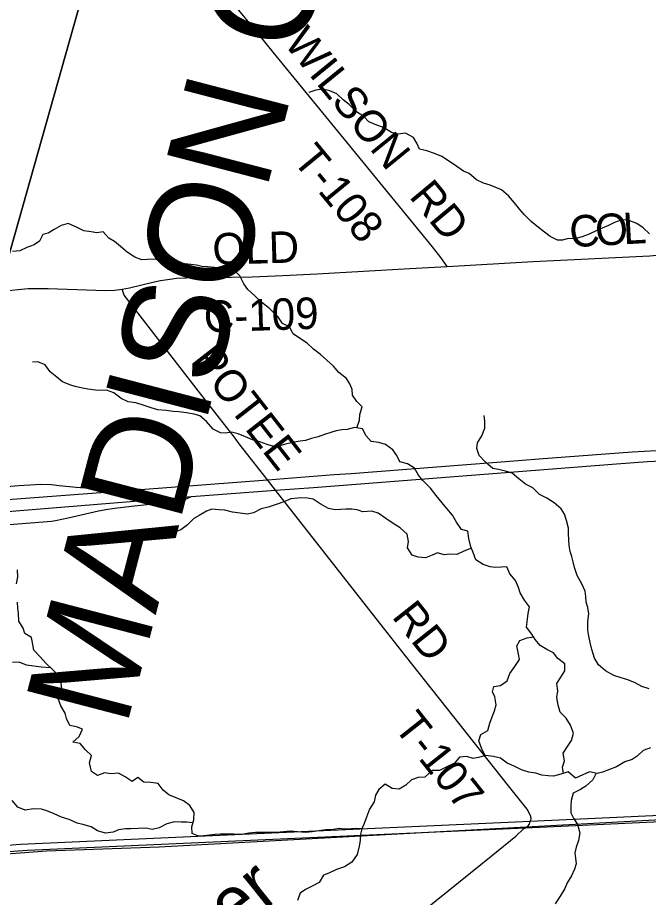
# Model space of a CAD drawing. Extents: x 0 to 36.5, y 0 to 25.3.
# Drawn here: x 2.661 to 3.798, y 17.166 to 18.753 of the extents above; entities that cross this region are included whole.
import ezdxf

# ---------------------------------------------------------------- set-up
doc = ezdxf.new("R2010")
doc.units = 0
for name, color, linetype in [('DV_X_Township_Line', 7, 'Continuous'), ('GM_X_County_Road', 7, 'Continuous'), ('GM_X_County_Road_Text', 7, 'Continuous'), ('GM_X_County_Text', 7, 'Continuous'), ('GM_X_Interchange_Ramps', 7, 'Continuous'), ('GM_X_Interstate_Route', 7, 'Continuous'), ('GM_X_Major_River', 7, 'Continuous'), ('GM_X_Major_River_Text', 7, 'Continuous'), ('GM_X_Minor_River', 7, 'Continuous'), ('GM_X_Rail_Line', 7, 'Continuous'), ('GM_X_Township_Road', 7, 'Continuous'), ('GM_X_Township_Road_Text', 7, 'Continuous'), ('GM_X_US_Route', 7, 'Continuous'), ('SH_Cut_Line', 7, 'Continuous')]:
    doc.layers.add(name, color=color, linetype=linetype)

msp = doc.modelspace()

# ---------------------------------------------------------------- linework, layer by layer
at = {"layer": 'DV_X_Township_Line'}
msp.add_lwpolyline([(3.3366, 20.9), (2.1, 20.9), (2.1, 17.5234), (2.4192, 17.4891), (2.5144, 17.8445), (2.5165, 17.8524), (2.5226, 17.8751), (2.5271, 17.8912), (2.6265, 18.2595), (2.8463, 19.037), (3.2612, 20.6041)], close=True, dxfattribs=at)
msp.add_lwpolyline([(4.5783, 20.9), (3.3366, 20.9), (3.2612, 20.6041), (2.8463, 19.037), (2.6265, 18.2595), (2.5271, 17.8912), (2.5226, 17.8751), (2.5165, 17.8524), (2.5144, 17.8445), (2.4192, 17.4891), (2.3437, 17.2326), (2.3403, 17.2198), (2.1039, 16.2931), (2.4938, 16.3413), (4.0938, 16.595), (4.8891, 16.7511), (5.1383, 16.6527), (6.6079, 15.9978)], dxfattribs=at)
at = {"layer": 'GM_X_County_Road'}
for points in [[(3.4349, 18.304), (3.5899, 18.3128), (3.8, 18.3234), (3.825, 18.3254), (3.8738, 18.3316), (3.8861, 18.3327), (3.8984, 18.3334), (3.9356, 18.3344), (4.072, 18.336), (4.1154, 18.3371), (4.1278, 18.338), (4.1464, 18.34), (4.1592, 18.3416)], [(2.8491, 18.263), (2.8623, 18.2657), (2.9045, 18.2756), (2.9184, 18.2785), (2.9349, 18.2814), (2.9472, 18.2828), (2.965, 18.2837), (3.0091, 18.2841), (3.0833, 18.2856), (3.139, 18.2877), (3.2008, 18.2908), (3.3675, 18.3004), (3.4349, 18.304)], [(2.6267, 18.259), (2.6615, 18.2628), (2.6797, 18.2643), (2.6857, 18.2645), (2.7161, 18.2642), (2.8192, 18.2609), (2.8351, 18.2612), (2.8491, 18.263)]]:
    msp.add_lwpolyline(points, dxfattribs=at)
at = {"layer": 'GM_X_Interchange_Ramps'}
for points in [[(2.8824, 17.9016), (2.8766, 17.9027), (2.8732, 17.903), (2.8494, 17.9027), (2.8096, 17.903), (2.7896, 17.9039), (2.7664, 17.9056), (2.7355, 17.9088), (2.7217, 17.9105), (2.7028, 17.9112), (2.663, 17.9087), (2.5819, 17.9019), (2.5689, 17.8995), (2.5273, 17.8906)], [(2.5146, 17.8439), (2.6098, 17.837), (2.6155, 17.8368), (2.6226, 17.8371), (2.722, 17.8447), (2.7293, 17.8458), (2.7517, 17.8506), (2.8066, 17.8635), (2.8233, 17.8666), (2.836, 17.8685), (2.8658, 17.8721), (2.9496, 17.8811), (2.956, 17.8822), (2.9622, 17.884), (2.9739, 17.889)]]:
    msp.add_lwpolyline(points, dxfattribs=at)
at = {"layer": 'GM_X_Interstate_Route'}
for points in [[(2.5228, 17.8746), (2.8824, 17.9016), (3.1111, 17.9191), (3.1262, 17.9203), (3.2312, 17.9287), (3.2621, 17.9308), (3.5708, 17.9546), (3.6, 17.9571), (3.7684, 17.9697), (3.8117, 17.9725), (3.8426, 17.974), (3.8859, 17.9757), (3.9231, 17.9763), (3.9912, 17.9767), (4.1622, 17.9727), (4.4, 17.967), (4.6257, 17.9616)], [(2.5168, 17.8519), (2.9739, 17.889), (3.1256, 17.9005), (3.1938, 17.9057), (3.7403, 17.9483), (3.7961, 17.9523), (3.8458, 17.9546), (3.883, 17.956), (3.9327, 17.957), (3.97, 17.9572), (4.001, 17.957), (4.0678, 17.9551), (4.1784, 17.9527), (4.324, 17.949), (4.3999, 17.9475)]]:
    msp.add_lwpolyline(points, dxfattribs=at)
at = {"layer": 'GM_X_Major_River'}
for points in [[(3.8012, 17.4362), (3.7883, 17.4313)], [(3.7883, 17.4313), (3.7775, 17.4208), (3.768, 17.4152), (3.7551, 17.4107), (3.7402, 17.4021), (3.7276, 17.3969), (3.7151, 17.3924), (3.7052, 17.3899), (3.6912, 17.393), (3.6793, 17.3874), (3.666, 17.3815), (3.6532, 17.393), (3.6399, 17.3885), (3.6266, 17.3852), (3.6167, 17.3857), (3.6054, 17.3869), (3.5948, 17.3904), (3.5819, 17.392), (3.5686, 17.3967), (3.5554, 17.4033), (3.5433, 17.4087), (3.5309, 17.4172), (3.5184, 17.4203), (3.504, 17.422), (3.4914, 17.4186), (3.4819, 17.4168), (3.4702, 17.4203), (3.4573, 17.4193), (3.4481, 17.4087), (3.4328, 17.4013), (3.421, 17.3953), (3.4077, 17.395), (3.3944, 17.383), (3.3826, 17.3827), (3.3708, 17.3786), (3.3605, 17.3688), (3.3483, 17.3617), (3.3357, 17.363), (3.3229, 17.3703), (3.3118, 17.3609), (3.306, 17.3507), (3.3033, 17.3389), (3.2948, 17.3257), (3.2894, 17.3109), (3.2855, 17.2999), (3.2812, 17.2901), (3.2785, 17.2802), (3.2784, 17.2692), (3.2764, 17.259), (3.2728, 17.2438), (3.2632, 17.2298), (3.2499, 17.2216), (3.2354, 17.2168), (3.2217, 17.2104), (3.2118, 17.2063), (3.2044, 17.1935), (3.1919, 17.1868), (3.1793, 17.1804), (3.1697, 17.174), (3.1651, 17.1608)]]:
    msp.add_lwpolyline(points, dxfattribs=at)
at = {"layer": 'GM_X_Minor_River'}
for points in [[(3.7997, 18.3628), (3.7881, 18.3735), (3.7768, 18.3816), (3.7609, 18.3878), (3.7495, 18.3883), (3.7362, 18.3834), (3.7255, 18.3778), (3.7141, 18.373), (3.7046, 18.3689), (3.6908, 18.3622), (3.6779, 18.3577), (3.6646, 18.354), (3.6528, 18.3545), (3.6429, 18.3512), (3.6335, 18.3516), (3.6206, 18.3578), (3.6104, 18.3659), (3.5965, 18.377), (3.5863, 18.3851), (3.5743, 18.3969), (3.5657, 18.4065), (3.5563, 18.4187), (3.5454, 18.4313), (3.5326, 18.4421), (3.5122, 18.4506), (3.5001, 18.4545), (3.488, 18.4603), (3.4744, 18.4714), (3.4646, 18.4761), (3.4521, 18.4842), (3.4393, 18.4934), (3.425, 18.5026), (3.4118, 18.508), (3.3981, 18.5127), (3.3853, 18.5158), (3.3801, 18.5265), (3.3741, 18.5364), (3.3597, 18.5445), (3.3457, 18.5424), (3.3343, 18.5455), (3.3204, 18.5547), (3.3079, 18.559), (3.2935, 18.5648), (3.2845, 18.5744), (3.2713, 18.5829), (3.2585, 18.5959), (3.2472, 18.6043), (3.2363, 18.6154), (3.2234, 18.6205), (3.2109, 18.624), (3.1984, 18.6222), (3.1855, 18.6178)], [(3.2723, 18.0128), (3.2769, 18.0272), (3.2777, 18.037), (3.282, 18.0511), (3.2723, 18.0603), (3.264, 18.0717), (3.2634, 18.082), (3.2593, 18.0923), (3.2537, 18.1018), (3.2394, 18.1126), (3.23, 18.124), (3.2183, 18.1352), (3.2066, 18.1451), (3.1942, 18.1551), (3.1825, 18.1658), (3.1708, 18.1735), (3.1576, 18.1824), (3.1506, 18.1954), (3.1381, 18.2015), (3.1295, 18.2138), (3.1152, 18.2279), (3.1005, 18.2394), (3.0881, 18.2509), (3.0757, 18.2628), (3.0685, 18.2728), (3.0615, 18.2869), (3.0494, 18.2987), (3.0354, 18.3015), (3.0252, 18.3012), (3.0157, 18.3021), (3.0032, 18.3033), (2.9929, 18.3042), (2.9831, 18.3061), (2.9729, 18.3074), (2.963, 18.3086), (2.9501, 18.3083), (2.9213, 18.3139), (2.9084, 18.3174), (2.8948, 18.3167), (2.8849, 18.3161), (2.872, 18.3207), (2.8585, 18.3296), (2.846, 18.3399), (2.8351, 18.3488), (2.8253, 18.3553), (2.8152, 18.3664), (2.8038, 18.3646), (2.7935, 18.3666), (2.7799, 18.3682), (2.767, 18.3748), (2.7519, 18.3814), (2.739, 18.3781), (2.7264, 18.3706), (2.7161, 18.3638), (2.7062, 18.3616), (2.7, 18.3495), (2.6905, 18.3431), (2.6776, 18.3383), (2.665, 18.3323), (2.6517, 18.3313)], [(2.8012, 18.0809), (2.7876, 18.0829), (2.7777, 18.0849), (2.7648, 18.0877), (2.755, 18.0904), (2.7418, 18.0962), (2.7316, 18.1047), (2.7192, 18.1143), (2.7102, 18.1265), (2.6973, 18.1323), (2.6878, 18.1312)], [(3.6447, 17.3901), (3.6427, 17.401), (3.6466, 17.4124), (3.644, 17.4265), (3.6517, 17.4382), (3.659, 17.4495), (3.6626, 17.4624), (3.6574, 17.4769), (3.6492, 17.4895), (3.6386, 17.5006), (3.635, 17.5132), (3.6324, 17.5269), (3.6341, 17.539), (3.6323, 17.552), (3.6407, 17.5652), (3.6469, 17.575), (3.647, 17.5875), (3.6342, 17.5971), (3.6263, 17.6071), (3.6142, 17.6133), (3.6022, 17.6206), (3.5932, 17.6313), (3.5876, 17.6409), (3.5778, 17.6539), (3.5795, 17.6683), (3.5807, 17.6781), (3.5831, 17.6903), (3.5741, 17.7021), (3.5666, 17.7155), (3.5637, 17.725), (3.5581, 17.7376), (3.5479, 17.7498), (3.5427, 17.7624), (3.5329, 17.7621), (3.5219, 17.7615), (3.5124, 17.7627), (3.4995, 17.7666), (3.4863, 17.7751), (3.4819, 17.7884), (3.4778, 17.7983), (3.4738, 17.8135), (3.4724, 17.8268), (3.4607, 17.83), (3.452, 17.843), (3.4446, 17.8559), (3.4344, 17.8678), (3.4258, 17.8781), (3.4149, 17.8912), (3.4048, 17.9045), (3.3913, 17.9179), (3.383, 17.9275), (3.3759, 17.9405), (3.3635, 17.9482), (3.3494, 17.9517), (3.3442, 17.9635), (3.3371, 17.9735), (3.3235, 17.9831), (3.3118, 17.9866), (3.2982, 17.9886), (3.2888, 17.9986), (3.2821, 18.0112), (3.268, 18.0136), (3.2547, 18.0103), (3.2452, 18.0096), (3.2346, 18.0078), (3.2251, 18.0044), (3.2141, 18.0011), (3.2023, 17.997), (3.1905, 17.9937), (3.1794, 17.9904), (3.1699, 17.9889), (3.1563, 17.9868), (3.1437, 17.9838), (3.1331, 17.9809), (3.1201, 17.9802), (3.1103, 17.983), (3.0971, 17.9876), (3.0842, 17.9912), (3.0717, 17.997), (3.0585, 18.0024), (3.046, 18.0055), (3.0357, 18.0037), (3.0263, 18.0038), (3.013, 18.0108), (3.001, 18.0245), (2.9894, 18.0349), (2.9788, 18.0376), (2.9651, 18.04), (2.9515, 18.0417), (2.9412, 18.0425), (2.9284, 18.0445), (2.9136, 18.0454), (2.9015, 18.0493), (2.8871, 18.054), (2.8738, 18.0583), (2.8602, 18.0599), (2.8477, 18.0657), (2.8342, 18.0761), (2.8209, 18.0811), (2.8111, 18.0804), (2.8012, 18.0809)], [(3.7991, 17.5422), (3.7859, 17.5465), (3.7738, 17.553), (3.7606, 17.5589), (3.7485, 17.5624), (3.7352, 17.5663), (3.7205, 17.5751), (3.7077, 17.5855), (3.7006, 17.5977), (3.6954, 17.6134), (3.6925, 17.6263), (3.6904, 17.6377), (3.6882, 17.6484), (3.6883, 17.6636), (3.69, 17.6776), (3.6882, 17.689), (3.6856, 17.6989), (3.6849, 17.7088), (3.6835, 17.7187), (3.6776, 17.732), (3.669, 17.7469), (3.6645, 17.7614), (3.662, 17.7713), (3.6594, 17.7808), (3.6565, 17.7904), (3.6547, 17.801), (3.654, 17.8113), (3.6537, 17.8227), (3.6534, 17.8322), (3.6501, 17.8463), (3.6464, 17.8573), (3.6405, 17.8672), (3.628, 17.878), (3.6145, 17.8864), (3.6012, 17.893), (3.5892, 17.9049), (3.576, 17.9118), (3.5643, 17.9211), (3.5519, 17.9314), (3.5401, 17.9349), (3.5273, 17.9377), (3.5174, 17.9397), (3.5042, 17.9512), (3.4926, 17.9634), (3.4882, 17.976), (3.4894, 17.9863), (3.4971, 17.9984), (3.5025, 18.0124), (3.5026, 18.0253), (3.5016, 18.0355)], [(3.4787, 17.7961), (3.4652, 17.7908), (3.4523, 17.7848), (3.439, 17.7853), (3.4295, 17.7843), (3.4174, 17.7874), (3.4079, 17.7837), (3.3961, 17.7785), (3.3828, 17.7797), (3.3718, 17.7832), (3.3632, 17.7966), (3.3652, 17.808), (3.3627, 17.8213), (3.3499, 17.8328), (3.3374, 17.8405), (3.3246, 17.8494), (3.3107, 17.8593), (3.2989, 17.8629), (3.283, 17.8619), (3.2728, 17.865), (3.2633, 17.8662), (3.2523, 17.8667), (3.2424, 17.866), (3.2329, 17.8653), (3.2208, 17.8677), (3.2061, 17.8758), (3.1936, 17.8846), (3.1804, 17.887), (3.166, 17.8864), (3.1531, 17.885), (3.1405, 17.8794), (3.1283, 17.8757), (3.1123, 17.8701), (3.0998, 17.8668), (3.086, 17.8601), (3.0743, 17.8575), (3.0618, 17.8595), (3.0481, 17.8612), (3.0341, 17.8647), (3.0242, 17.8652), (3.011, 17.8664), (3.0011, 17.8631), (2.9881, 17.8552), (2.9786, 17.8496), (2.9667, 17.8379), (2.9552, 17.8293), (2.9415, 17.8241), (2.9283, 17.828), (2.9161, 17.8239), (2.9051, 17.8229), (2.8922, 17.823)], [(2.6588, 17.7318), (2.6612, 17.7444), (2.6605, 17.7569)], [(3.2812, 17.29), (3.2721, 17.2906), (3.2626, 17.2903), (3.2497, 17.2896), (3.2402, 17.2904), (3.23, 17.289), (3.2163, 17.2884), (3.2038, 17.2866), (3.1916, 17.2844), (3.1795, 17.2834), (3.1654, 17.2846), (3.1518, 17.2859), (3.14, 17.2844), (3.1275, 17.2834), (3.1142, 17.2835), (3.1017, 17.2836), (3.0895, 17.2837), (3.0774, 17.2823), (3.0641, 17.2798), (3.0504, 17.2806), (3.0406, 17.2803), (3.0269, 17.2805), (3.0167, 17.2798), (3.0064, 17.2787), (2.9965, 17.2777), (2.987, 17.2766), (2.9753, 17.2817), (2.975, 17.2938), (2.9782, 17.3063), (2.9787, 17.3192), (2.9712, 17.3322), (2.9595, 17.3407), (2.9463, 17.3457), (2.9331, 17.3512), (2.9229, 17.3596), (2.9139, 17.3718), (2.901, 17.3735), (2.8885, 17.3739), (2.8772, 17.3828), (2.8673, 17.3753), (2.8548, 17.3837), (2.8427, 17.3903), (2.8287, 17.3893), (2.8173, 17.3913), (2.8048, 17.3864), (2.7942, 17.3934), (2.7902, 17.409), (2.7937, 17.4222), (2.7832, 17.4322), (2.7734, 17.4441), (2.7605, 17.4464), (2.7716, 17.4566), (2.7778, 17.4695), (2.7672, 17.4741), (2.7551, 17.4765), (2.7488, 17.4891), (2.7462, 17.4986), (2.7384, 17.512), (2.7339, 17.5253), (2.7413, 17.5385), (2.7395, 17.5519), (2.7354, 17.5656), (2.7238, 17.5771), (2.7125, 17.5882), (2.7009, 17.6008), (2.6899, 17.6119), (2.6885, 17.6222), (2.6856, 17.6351), (2.6739, 17.6424), (2.671, 17.652), (2.6631, 17.6646), (2.6621, 17.6786), (2.661, 17.6881), (2.6604, 17.6988)], [(3.5035, 17.4218), (3.4965, 17.4357), (3.4917, 17.4486), (3.4956, 17.46), (3.5082, 17.4671), (3.5117, 17.4808), (3.516, 17.4921), (3.5199, 17.5027), (3.5234, 17.5137), (3.5205, 17.5278), (3.5168, 17.5373), (3.5188, 17.5468), (3.5309, 17.5482), (3.5428, 17.5569), (3.5478, 17.5701), (3.557, 17.5826), (3.5655, 17.5951), (3.5633, 17.605), (3.5604, 17.6198), (3.5658, 17.6296), (3.5788, 17.6345), (3.5902, 17.6364)], [(2.7207, 17.5801), (2.703, 17.5818), (2.6901, 17.5834), (2.6768, 17.5851), (2.6636, 17.5905), (2.6518, 17.5902)], [(3.7033, 17.3903), (3.6975, 17.3782), (3.6845, 17.3672), (3.6749, 17.3612), (3.662, 17.3541), (3.6581, 17.3409), (3.6576, 17.3314), (3.6575, 17.3188), (3.6623, 17.3093), (3.6698, 17.2978), (3.6738, 17.283), (3.6714, 17.2693), (3.6672, 17.2568), (3.6652, 17.2466), (3.6662, 17.2371), (3.6673, 17.2272), (3.6641, 17.2174), (3.6591, 17.2052), (3.6514, 17.1924), (3.6467, 17.1822), (3.6383, 17.1689), (3.6298, 17.155)], [(2.9768, 17.301), (2.966, 17.3019), (2.9554, 17.3023), (2.9433, 17.3024), (2.9299, 17.2991), (2.9158, 17.2917), (2.9033, 17.2891), (2.8916, 17.2915), (2.8779, 17.2908), (2.865, 17.2898), (2.8551, 17.2899), (2.8426, 17.2881), (2.8327, 17.284), (2.8194, 17.2822), (2.805, 17.2865), (2.7933, 17.2938), (2.7785, 17.2978), (2.7683, 17.3001), (2.7536, 17.3067), (2.74, 17.311), (2.7267, 17.3168), (2.7135, 17.3222), (2.7037, 17.3254), (2.6893, 17.3262), (2.6744, 17.3237), (2.6612, 17.3291), (2.6507, 17.3414)]]:
    msp.add_lwpolyline(points, dxfattribs=at)
at = {"layer": 'GM_X_Rail_Line'}
msp.add_lwpolyline([(4.8132, 17.3633), (4.4331, 17.3456), (4.2941, 17.3319), (2.916, 17.2571), (2.713, 17.2498), (2.6011, 17.2415), (2.3443, 17.2175)], dxfattribs=at)
at = {"layer": 'GM_X_Township_Road'}
for points in [[(3.4349, 18.304), (3.4237, 18.3202), (3.4085, 18.3397), (3.1214, 18.6905), (3.0861, 18.7343), (3.0621, 18.7634), (3.0487, 18.7805), (2.9904, 18.8512), (2.9547, 18.8951), (2.8824, 18.9881), (2.8465, 19.0365)], [(3.0248, 18.0305), (2.9824, 18.0845), (2.8528, 18.2522), (2.8491, 18.263)], [(3.3202, 17.6522), (3.1256, 17.9005), (3.1111, 17.9191), (3.0601, 17.9841), (3.0512, 17.9968), (3.0248, 18.0305)], [(3.5455, 17.3678), (3.3598, 17.6017), (3.3202, 17.6522)], [(3.5847, 17.3036), (3.586, 17.3075), (3.5857, 17.3128), (3.579, 17.3255), (3.5455, 17.3678)], [(2.5272, 16.3696), (2.6732, 16.4737), (2.7817, 16.5545), (3.0089, 16.7361), (3.0189, 16.7463), (3.0254, 16.7567), (3.0317, 16.7741), (3.055, 16.8575), (3.0601, 16.8689), (3.0713, 16.8835), (3.5173, 17.2429), (3.5586, 17.2771), (3.5726, 17.2899), (3.5758, 17.292)], [(3.5758, 17.292), (3.5805, 17.2951), (3.5832, 17.2987), (3.5847, 17.3036)]]:
    msp.add_lwpolyline(points, dxfattribs=at)
at = {"layer": 'GM_X_US_Route'}
for points in [[(2.3439, 17.2321), (2.6041, 17.2573), (2.666, 17.2624), (3.5847, 17.3036), (4.2468, 17.3347)], [(2.3405, 17.2192), (2.6107, 17.2468), (2.6789, 17.2516), (3.5758, 17.292), (4.2432, 17.3229)]]:
    msp.add_lwpolyline(points, dxfattribs=at)
at = {"layer": 'SH_Cut_Line'}
msp.add_lwpolyline([(3.3366, 20.9), (2.1, 20.9), (2.1, 16.2788), (2.1039, 16.2931), (2.3403, 17.2198), (2.3437, 17.2326), (2.4192, 17.4891), (2.5144, 17.8445), (2.5165, 17.8524), (2.5226, 17.8751), (2.5271, 17.8912), (2.6265, 18.2595), (2.8463, 19.037), (3.2612, 20.6041)], close=True, dxfattribs=at)
msp.add_lwpolyline([(4.4591, 20.9), (3.3366, 20.9), (3.2612, 20.6041), (2.8463, 19.037), (2.6265, 18.2595), (2.5271, 17.8912), (2.5226, 17.8751), (2.5165, 17.8524), (2.5144, 17.8445), (2.4192, 17.4891), (2.3437, 17.2326), (2.3403, 17.2198), (2.1039, 16.2931), (2.1, 16.2788), (2.1, 14.1), (8.9, 14.1), (8.9, 20.9), (6.1845, 20.9)], dxfattribs=at)

# ---------------------------------------------------------------- texts
at = {"layer": 'GM_X_County_Road_Text'}
for s, height, rotation, p in [('C', 0.0568, 3.1279, (3.6565, 18.3386)), ('O', 0.0568, 3.1271, (3.7031, 18.3411)), ('L', 0.0568, 3.2282, (3.7531, 18.3439)), ('OLD', 0.05682, 1.6466, (3.0126, 18.3069)), ('C-109', 0.05682, 1.9182, (2.9972, 18.185))]:
    msp.add_text(s, height=height, rotation=rotation, dxfattribs=at).set_placement(p)
at = {"layer": 'GM_X_County_Text'}
msp.add_text('MADISON COUNTY', height=0.189394, rotation=75.3839, dxfattribs=at).set_placement((2.8562, 17.4706))
at = {"layer": 'GM_X_Major_River_Text'}
msp.add_text('Deer', height=0.09472, rotation=38.682, dxfattribs=at).set_placement((2.9237, 16.9969))
at = {"layer": 'GM_X_Township_Road_Text'}
for s, rotation, p in [('WILSON', 309.1687, (3.1391, 18.7062)), ('T-108', 309.4077, (3.1548, 18.4953)), ('RD', 309.7425, (3.3648, 18.4297)), ('POTEE', 307.9714, (2.9729, 18.1348)), ('RD', 308.4279, (3.3337, 17.6723)), ('T-107', 308.4414, (3.3371, 17.4732))]:
    msp.add_text(s, height=0.05682, rotation=rotation, dxfattribs=at).set_placement(p)

doc.saveas('drawing.dxf')
